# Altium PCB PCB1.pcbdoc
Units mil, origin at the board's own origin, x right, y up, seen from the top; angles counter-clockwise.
Board outline 1023.62 x 2480.31 mil, 4 copper layers (Top Layer, Inner2, Inner3, Bottom Layer), stack 62.447 mil thick; 59 components, 53 nets, 271 pads, 114 vias.
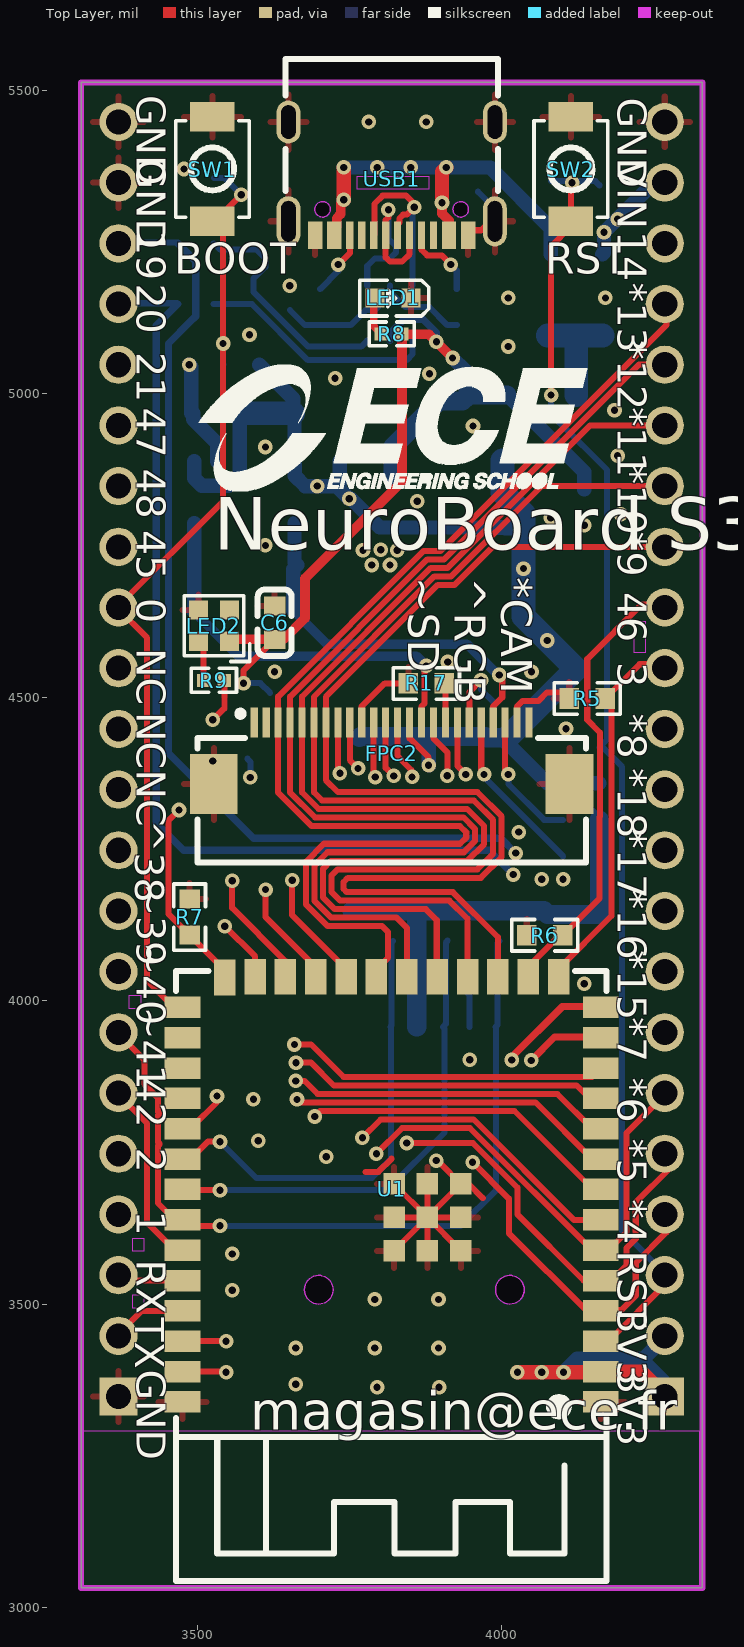
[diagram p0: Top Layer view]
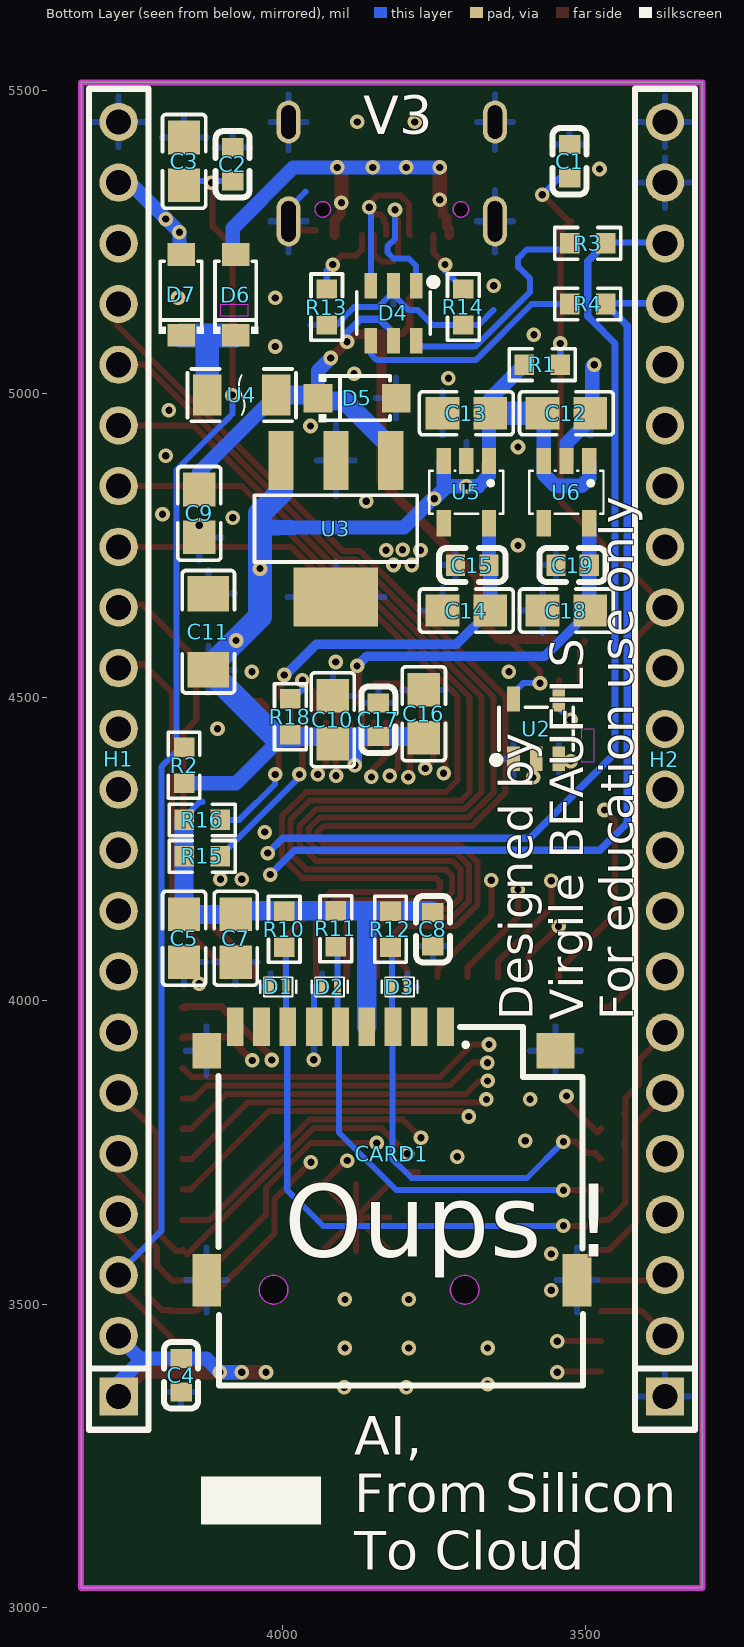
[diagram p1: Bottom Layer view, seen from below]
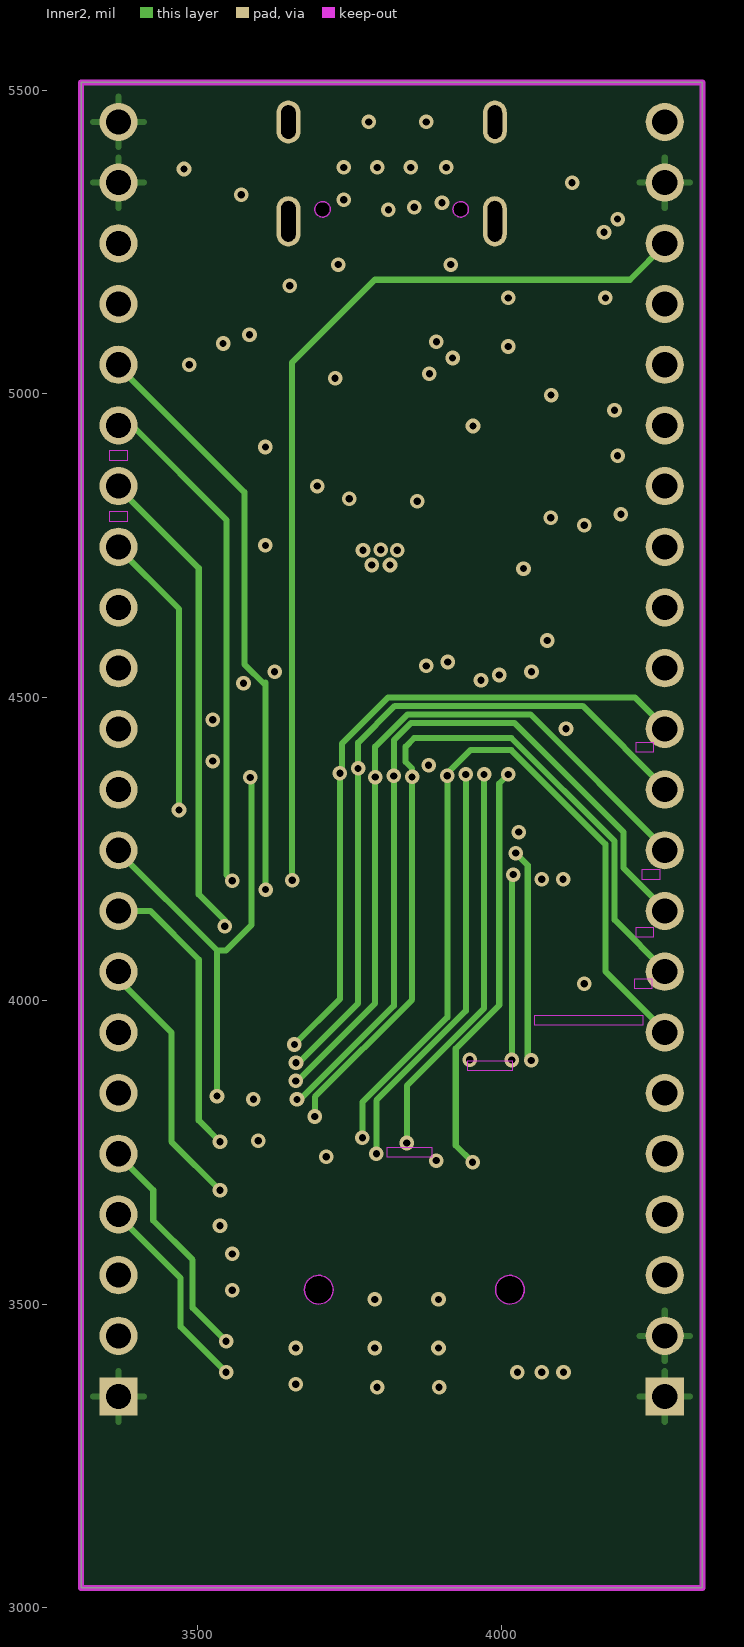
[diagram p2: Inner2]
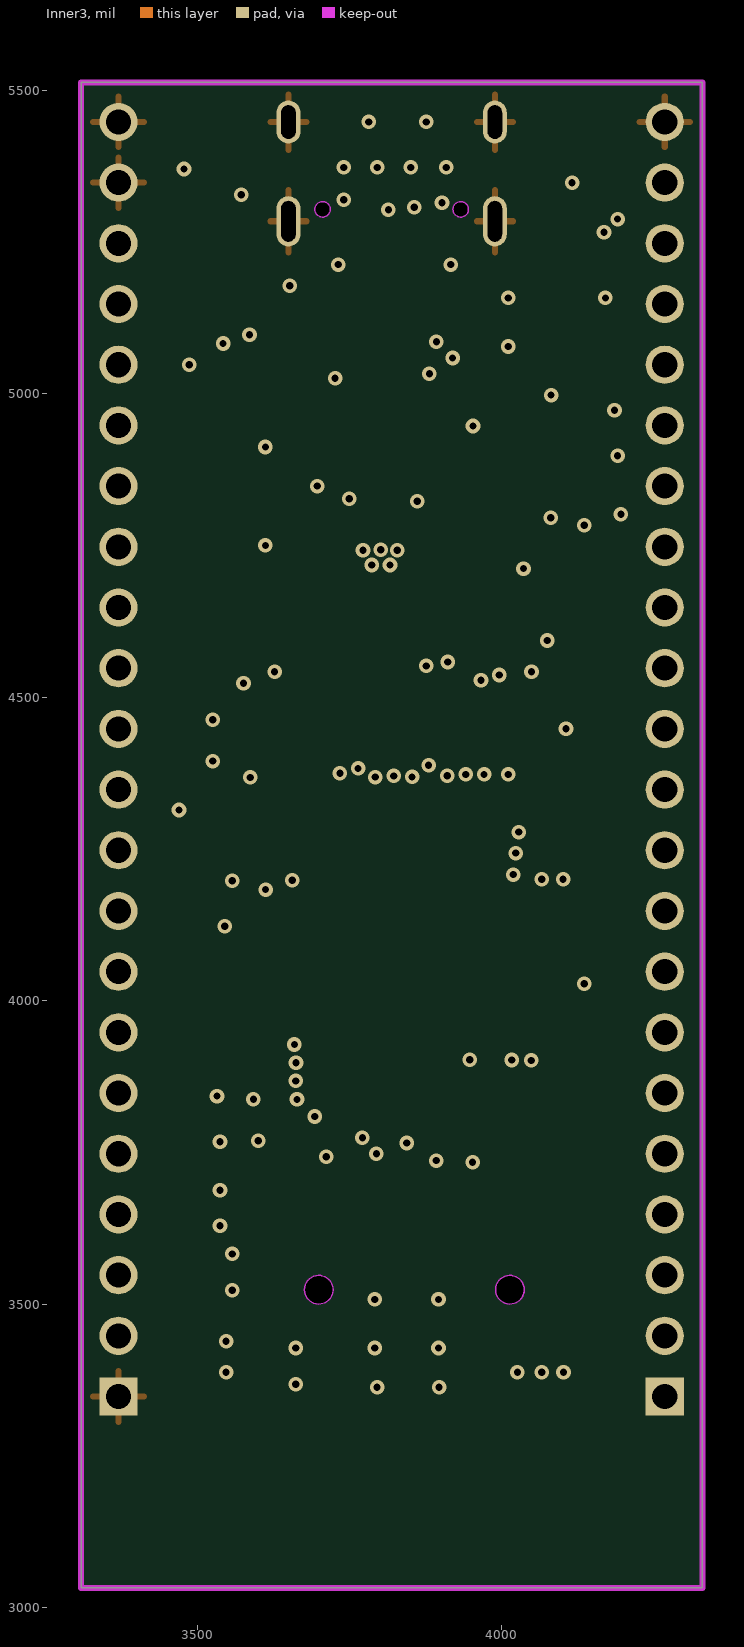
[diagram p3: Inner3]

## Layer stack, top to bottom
Top Layer: signal copper 1.378
Dielectric1: surface 8.283, 7628 RC49% 8.6mil, Dk 0
Inner2: signal copper 0.598
Dielectric2: surface 41.929, 1.1mm H/HOZ Copper, Dk 0
Inner3: signal copper 0.598
Dielectric3: surface 8.283, 7628 RC49% 8.6mil, Dk 0
Bottom Layer: signal copper 1.378

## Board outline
3307.99,5513.17 3307.99,3032.85 4331.61,3032.85 4331.61,5513.17

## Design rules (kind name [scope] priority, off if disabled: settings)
BoardOutlineClearance copperThickness1oz [All] p0: genericclearance=10 ignorepadtopadclearanceinfootprint=FALSE except(0: Arc-SplitContinuation Track-SplitContinuation SMDPad-SplitContinuation THPad-SplitContinuation Via-SplitContinuation Fill-SplitContinuation Poly-SplitContinuation Region-SplitContinuation Text-SplitContinuation)
BoardOutlineClearance copperThickness2oz [All] p0: genericclearance=10 ignorepadtopadclearanceinfootprint=FALSE except(0: Arc-SplitContinuation Track-SplitContinuation SMDPad-SplitContinuation THPad-SplitContinuation Via-SplitContinuation Fill-SplitContinuation Poly-SplitContinuation Region-SplitContinuation Text-SplitContinuation)
BoardOutlineClearance Plane_innerPlane [All] p0: genericclearance=10 ignorepadtopadclearanceinfootprint=FALSE except(0: Arc-SplitContinuation Track-SplitContinuation SMDPad-SplitContinuation THPad-SplitContinuation Via-SplitContinuation Fill-SplitContinuation Poly-SplitContinuation Region-SplitContinuation Text-SplitContinuation)
BoardOutlineClearance Copper_copperRegion [All] p0: genericclearance=10 ignorepadtopadclearanceinfootprint=FALSE except(0: Arc-SplitContinuation Track-SplitContinuation SMDPad-SplitContinuation THPad-SplitContinuation Via-SplitContinuation Fill-SplitContinuation Poly-SplitContinuation Region-SplitContinuation Text-SplitContinuation)
BoardOutlineClearance otherClearance [All] p0: genericclearance=10 ignorepadtopadclearanceinfootprint=FALSE except(0: Arc-SplitContinuation Track-SplitContinuation SMDPad-SplitContinuation THPad-SplitContinuation Via-SplitContinuation Fill-SplitContinuation Poly-SplitContinuation Region-SplitContinuation Text-SplitContinuation)
Clearance copperThickness1oz [All] p1: gap=7 ignorepadtopadclearanceinfootprint=FALSE
Clearance copperThickness2oz [All] p1: gap=7 ignorepadtopadclearanceinfootprint=FALSE
Clearance Plane_innerPlane [All] p1: gap=7 ignorepadtopadclearanceinfootprint=FALSE
Clearance Copper_copperRegion [All] p1: gap=7 ignorepadtopadclearanceinfootprint=FALSE
Clearance otherClearance [All] p1: gap=7 ignorepadtopadclearanceinfootprint=FALSE
DiffPairsRouting differentialPair [All] p1: maxuncoupledlength=10 minlimit=6 maxlimit=Infinity mostfreqgap=6 toplayer_minwidth=5 toplayer_prefwidth=10 toplayer_maxwidth=100 bottomlayer_minwidth=5 bottomlayer_prefwidth=10 bottomlayer_maxwidth=100 midlayer2_minwidth=5 midlayer2_prefwidth=10 midlayer2_maxwidth=100 midlayer3_minwidth=5 midlayer3_prefwidth=10 midlayer3_maxwidth=100
PasteMaskExpansion pasteMaskExpansion [All] p1: expansion=0
PlaneConnect innerPlane [All] p1: planeconnectstyle=Relief reliefexpansion=20 reliefentries=4 reliefconductorwidth=10 reliefairgap=10
PolygonConnect copperRegion [All] p1: connectstyle=Relief reliefentries=4 reliefconductorwidth=10 polygonreliefangle="90 Angle" airgapwidth=10
RoutingVias viaSize [All] p1: viastyle="Through Hole" holewidth=12.0078 minholewidth=11.811 maxholewidth=248.0314 width=12.0078 minwidth=11.811 maxwidth=248.0314
SolderMaskExpansion solderMaskExpansion [IsVia] p1: useseparateexpansions=TRUE expansion=-1000 expansionbottom=-1000
SolderMaskExpansion solderMaskExpansion [All] p2: useseparateexpansions=TRUE expansion=2 expansionbottom=2
Width copperThickness1oz [All] p1: maxlimit=100 minlimit=5 preferedwidth=10
Width copperThickness2oz [All] p1: maxlimit=100 minlimit=8 preferedwidth=10

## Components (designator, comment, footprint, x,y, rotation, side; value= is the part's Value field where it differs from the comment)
C1 "100nF" C0603 3526.89,5382.99 r90 bottom
C2 "100nF" C0603 4081.89,5377.99 r90 bottom
C3 "1uF" C0805 4161.89,5382.99 r270 bottom
C4 "100nF" C0603 4166.89,3382.99 r90 bottom
C5 "22uF" C0805 4161.89,4102.99 r90 bottom
C6 "100nF" C0603 3626.89,4622.99 r270 top
C7 "10uF" C0805 4076.89,4102.99 r270 bottom
C8 "100nF" C0603 3751.89,4117.99 r270 bottom
C9 "10uF" C0805 4136.89,4802.99 r270 bottom
C10 "10uF" C0805 3916.89,4462.99 r90 bottom
C11 "47uF" C1206 4121.89,4607.99 r270 bottom
C12 "1uF" C0805 3531.89,4967.99 r0 bottom
C13 "1uF" C0805 3696.89,4967.99 r180 bottom
C14 "10uF" C0805 3696.89,4642.99 r0 bottom
C15 "100nF" C0603 3686.89,4717.99 r0 bottom
C16 "10uF" C0805 3766.89,4472.99 r90 bottom
C17 "100nF" C0603 3841.89,4462.99 r90 bottom
C18 "10uF" C0805 3531.89,4642.99 r0 bottom
C19 "100nF" C0603 3521.89,4717.99 r0 bottom
CARD1 "TF PUSH" TF-SMD_TF-PUSH 3819.65,3748.39 r180 bottom locked
D1 "LESD8D3.3CAT5G" SOD-882_L1.0-W0.6-BI 4006.89,4022.99 r180 bottom
D2 "LESD8D3.3CAT5G" SOD-882_L1.0-W0.6-BI 3921.89,4022.99 r180 bottom
D3 "LESD8D3.3CAT5G" SOD-882_L1.0-W0.6-BI 3806.89,4022.99 r0 bottom
D4 "USBLC6-2SC6" SOT-23-6_L2.9-W1.6-P0.95-LS2.8-BL 3816.89,5132.99 r0 bottom
D5 "SMF5.0A" SOD-123FL_L2.7-W1.8-LS3.8-RD 3876.89,4992.99 r180 bottom
D6 "DSS34" SOD-123_L2.8-W1.8-LS3.7-RD-2 4076.89,5162.99 r90 bottom
D7 "DSS34" SOD-123_L2.8-W1.8-LS3.7-RD-2 4166.89,5162.99 r90 bottom
FPC2 "FPC-05F-24PH20" FPC-SMD_24P-P0.50_FPC-05F-24PH20 3819.65,4407.99 r0 top locked
H1 "B-2100S22P-A110" HDR-TH_22P-P2.54-V-M 4269.65,4397.99 r90 bottom locked
H2 "B-2100S22P-A110" HDR-TH_22P-P2.54-V-M 3369.65,4397.99 r90 bottom locked
LED1 "KT-0603B" LED0603-RD 3821.89,5157.99 r180 top
LED2 "SK6805-EC20" LED-SMD_4P-L2.0-W2.0-BR 3526.89,4617.99 r0 top
R1 "10kΩ" R0603 3571.89,5047.99 r0 bottom
R2 "10kΩ" R0603 4161.89,4387.99 r270 bottom
R3 "" R0603 3496.89,5247.99 r180 bottom
R4 "" R0603 3496.89,5147.99 r180 bottom
R5 "10kΩ" R0603 4141.89,4497.99 r180 top
R6 "10kΩ" R0603 4071.89,4107.99 r180 top
R7 "10kΩ" R0603 3486.89,4137.99 r270 top
R8 "1kΩ" R0402 3819.65,5098.78 r0 top
R9 "220Ω" R0402 3526.89,4527.99 r0 top
R10 "10kΩ" R0603 3996.89,4117.99 r270 bottom
R11 "10kΩ" R0603 3911.89,4118.67 r270 bottom
R12 "10kΩ" R0603 3821.89,4117.99 r270 bottom
R13 "5.1kΩ" R0603 3926.89,5142.99 r90 bottom
R14 "5.1kΩ" R0603 3701.89,5142.99 r90 bottom
R15 "2.7kΩ" R0603 4131.89,4237.99 r0 bottom
R16 "2.7kΩ" R0603 4131.89,4297.99 r0 bottom
R17 "10kΩ" R0603 3876.89,4522.99 r180 top
R18 "10kΩ" R0603 3986.89,4467.99 r270 bottom
SW1 "TS-1088-AR02016" SW-SMD_L3.9-W3.0-P4.45 3524.37,5370.43 r270 top
SW2 "TS-1088-AR02016" SW-SMD_L3.9-W3.0-P4.45 4114.92,5370.43 r270 top locked
U1 "2.4GHz" WIRELM-SMD_ESP32-S3-WROOM-1 3819.65,3689.33 r180 top locked
U2 "SN74AHCT1G125DBVR(UMW)" SOT-23-5_L3.0-W1.5-P0.95-LS2.8-BL 3581.89,4447.99 r180 bottom
U3 "AP7361C-33E-13" SOT-223_L6.5-W3.5-P2.30-LS7.0-BR 3911.89,4777.99 r90 bottom
U4 "MF-NSMF150-2" F1206 4066.89,4997.99 r0 bottom
U5 "ME6211C28M5G-N" SOT-23-5_L3.0-W1.7-P0.95-LS2.8-BR 3696.89,4837.99 r90 bottom
U6 "ME6211C15M5G-N" SOT-23-5_L3.0-W1.7-P0.95-LS2.8-BR 3531.89,4837.99 r90 bottom
USB1 "TYPE-C16PIN" USB-C-SMD_TYPE-C16PIN 3819.65,5354.69 r180 top locked

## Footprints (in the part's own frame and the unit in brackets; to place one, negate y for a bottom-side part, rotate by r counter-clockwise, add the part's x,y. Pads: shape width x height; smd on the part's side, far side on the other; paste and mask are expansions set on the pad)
C0603 [mm]
  rect 0.8x0.9 smd: 1(-0.7,0) 2(0.7,0)
  silkscreen extent -1.39,-0.71 1.39,0.71
C0805 [mm]
  rect 1.41x1.35 smd paste-100 mask+0.051: 1(-1,0) 2(1,0)
  silkscreen extent -1.96,-0.9 1.96,0.9
C1206 [mm]
  rect 1.485x1.728 smd paste-100 mask+0.051: 1(-1.593,0) 2(1.593,0)
  silkscreen extent -2.56,-1.09 2.56,1.09
F1206 [mm]
  rect 1.19x1.728 smd: 1(-1.445,0) 2(1.445,0)
  silkscreen extent -2.27,-1.09 2.27,1.09
FPC-SMD_24P-P0.50_FPC-05F-24PH20 [mm]
  rect 0.3x1.25 smd paste+0 mask+0.05: 1(-5.75,1.288) 2(-5.25,1.288) 3(-4.75,1.288) 4(-4.25,1.288) 5(-3.75,1.288) 6(-3.25,1.288) 7(-2.75,1.288) 8(-2.25,1.288) 9(-1.75,1.288) 10(-1.25,1.288) 11(-0.75,1.288) 12(-0.25,1.288) 13(0.25,1.288) 14(0.75,1.288) 15(1.25,1.288) 16(1.75,1.288) 17(2.25,1.288) 18(2.75,1.288) 19(3.25,1.288) 20(3.75,1.288) 21(4.25,1.288) 22(4.75,1.288) 23(5.25,1.288) 24(5.75,1.288)
  rect 2x2.5 smd paste+0 mask+0.05: 25(7.44,-1.288) 26(-7.44,-1.288)
  silkscreen extent -8.13,-4.57 8.13,1.78
HDR-TH_22P-P2.54-V-M [mm]
  rect 1.6x1.6 hole 1.05: 1(-26.67,0)
  round 1.6 hole 1.05: 2(-24.13,0) 3(-21.59,0) 4(-19.05,0) 5(-16.51,0) 6(-13.97,0) 7(-11.43,0) 8(-8.89,0) 9(-6.35,0) 10(-3.81,0) 11(-1.27,0) 12(1.27,0) 13(3.81,0) 14(6.35,0) 15(8.89,0) 16(11.43,0) 17(13.97,0) 18(16.51,0) 19(19.05,0) 20(21.59,0) 21(24.13,0) 22(26.67,0)
  silkscreen extent -28.06,-1.25 28.06,1.25
LED0603-RD [mm]
  rect 0.8x0.8 smd: 1(-0.749,0) 2(0.749,0)
  silkscreen extent -1.49,-0.75 1.39,0.76
LED-SMD_4P-L2.0-W2.0-BR [mm]
  rect 0.8x0.8 smd: 1(0.65,-0.65) 2(0.65,0.65) 3(-0.65,0.65) 4(-0.65,-0.65)
  silkscreen extent -1.25,-1.5 1.5,1.25
R0402 [mm]
  rect 0.566x0.54 smd paste-100 mask+0.051: 1(-0.433,0) 2(0.433,0)
  silkscreen extent -0.94,-0.5 0.94,0.5
R0603 [mil]
  rect 31.75x34.02 smd paste-3937.01 mask+2: 1(-29.66,0) 2(29.66,0)
  silkscreen extent -55,-26 55,26
SOD-123_L2.8-W1.8-LS3.7-RD-2 [mm]
  rect 0.95x1.15 smd: 1(-1.692,0) 2(1.692,0)
  silkscreen extent -1.63,-0.94 1.41,0.94
SOD-123FL_L2.7-W1.8-LS3.8-RD [mm]
  rect 1.2x1.2 smd: 1(-1.635,0) 2(1.635,0)
  silkscreen extent -1.6,-1 1.38,1
SOD-882_L1.0-W0.6-BI [mm]
  rect 0.3x0.6 smd paste+0 mask+0.05: 1(-0.325,0) 2(0.325,0)
  silkscreen extent -0.75,-0.4 0.75,0.4
SOT-23-5_L3.0-W1.5-P0.95-LS2.8-BL [mm]
  rect 0.532x1.045 smd: 1(-0.95,-1.25) 2(0,-1.25) 3(0.95,-1.25) 4(0.95,1.25) 5(-0.95,1.25)
  silkscreen extent -1.82,-1.45 1.55,0.9
SOT-23-5_L3.0-W1.7-P0.95-LS2.8-BR [mm]
  rect 1.1x0.6 smd: 1(1.3,-0.95) 2(1.3,0) 3(1.3,0.95) 4(-1.3,0.95) 5(-1.3,-0.95)
  silkscreen extent -0.9,-1.55 0.9,1.55
SOT-23-6_L2.9-W1.6-P0.95-LS2.8-BL [mil]
  rect 20.95x42.2 smd: 1(-37.4,-45.24) 2(0,-45.24) 3(37.4,-45.24) 4(37.4,45.24) 5(0,45.24) 6(-37.4,45.24)
  silkscreen extent -72,-57 61,35
SOT-223_L6.5-W3.5-P2.30-LS7.0-BR [mm]
  rect 2.465x1.05 smd: 1(2.857,-2.3) 2(2.857,0) 3(2.857,2.3)
  rect 2.465x3.54 smd: 4(-2.857,0)
  silkscreen extent -1.4,-3.4 1.4,3.4
SW-SMD_L3.9-W3.0-P4.45 [mm]
  rect 1.23x1.86 smd: 1(-2.185,0) 2(2.185,0)
  silkscreen extent -2.03,-1.54 2.03,1.54
TF-SMD_TF-PUSH [mm]
  rect 0.7x1.6 smd: 1(2.25,5.3) 2(1.15,5.3) 3(0.05,5.3) 4(-1.05,5.3) 5(-2.15,5.3) 6(-3.25,5.3) 7(-4.35,5.3) 8(-5.45,5.3) CD(-6.55,5.3)
  rect 1.2x1.5 smd: 10(-7.75,4.3)
  rect 1.2x2.2 smd: 11(-7.75,-5.3) 12(7.75,-5.3)
  rect 1.6x1.5 smd: 13(6.85,4.3)
  Board Outline Layer circle w0.003: c-4.95,-5.7 r0.6
  Board Outline Layer circle w0.003: c3.05,-5.7 r0.6
  Board Outline Layer region: -5.55,-5.7 -5.491,-5.96 -5.324,-6.169 -5.083,-6.285 -4.816,-6.285 -4.576,-6.169 -4.409,-5.96 -4.35,-5.7 -4.35,-5.7 -4.409,-5.44 -4.576,-5.231 -4.816,-5.115 -5.083,-5.115 -5.324,-5.231 -5.491,-5.44 -5.55,-5.7
  Board Outline Layer region: -5.55,-5.7 -5.541,-5.804 -5.514,-5.905 -5.47,-6 -5.41,-6.086 -5.336,-6.16 -5.25,-6.22 -5.155,-6.264 -5.054,-6.291 -4.95,-6.3 -4.846,-6.291 -4.745,-6.264 -4.65,-6.22 -4.564,-6.16 -4.49,-6.086 -4.43,-6 -4.386,-5.905 -4.359,-5.804 -4.35,-5.7 -4.359,-5.596 -4.386,-5.495 -4.43,-5.4 -4.49,-5.314 -4.564,-5.24 -4.65,-5.18 -4.745,-5.136 -4.846,-5.109 -4.95,-5.1 -5.054,-5.109 -5.155,-5.136 -5.25,-5.18 -5.336,-5.24 -5.41,-5.314 -5.47,-5.4 -5.514,-5.495 -5.541,-5.596
  Board Outline Layer region: 2.45,-5.7 2.509,-5.96 2.676,-6.169 2.917,-6.285 3.184,-6.285 3.424,-6.169 3.591,-5.96 3.65,-5.7 3.65,-5.7 3.591,-5.44 3.424,-5.231 3.184,-5.115 2.917,-5.115 2.676,-5.231 2.509,-5.44 2.45,-5.7
  Board Outline Layer region: 2.45,-5.7 2.459,-5.804 2.486,-5.905 2.53,-6 2.59,-6.086 2.664,-6.16 2.75,-6.22 2.845,-6.264 2.946,-6.291 3.05,-6.3 3.154,-6.291 3.255,-6.264 3.35,-6.22 3.436,-6.16 3.51,-6.086 3.57,-6 3.614,-5.905 3.641,-5.804 3.65,-5.7 3.641,-5.596 3.614,-5.495 3.57,-5.4 3.51,-5.314 3.436,-5.24 3.35,-5.18 3.255,-5.136 3.154,-5.109 3.05,-5.1 2.946,-5.109 2.845,-5.136 2.75,-5.18 2.664,-5.24 2.59,-5.314 2.53,-5.4 2.486,-5.495 2.459,-5.596
  Multi-Layer board cut-out: -5.55,-5.7 -5.491,-5.96 -5.324,-6.169 -5.083,-6.285 -4.816,-6.285 -4.576,-6.169 -4.409,-5.96 -4.35,-5.7 -4.35,-5.7 -4.409,-5.44 -4.576,-5.231 -4.816,-5.115 -5.083,-5.115 -5.324,-5.231 -5.491,-5.44 -5.55,-5.7
  Multi-Layer board cut-out: 2.45,-5.7 2.509,-5.96 2.676,-6.169 2.917,-6.285 3.184,-6.285 3.424,-6.169 3.591,-5.96 3.65,-5.7 3.65,-5.7 3.591,-5.44 3.424,-5.231 3.184,-5.115 2.917,-5.115 2.676,-5.231 2.509,-5.44 2.45,-5.7
  silkscreen extent -7.26,-9.7 8,5.3
USB-C-SMD_TYPE-C16PIN [mm]
  oval 1x2.1 hole 0.6 slot 1.7 at 90 deg: 1(-4.32,1.787) 2(4.32,1.787)
  oval 1x1.8 hole 0.6 slot 1.4 at 90 deg: 3(-4.32,-2.362) 4(4.32,-2.362)
  rect 0.6x1.15 smd paste-100 mask+0.051: A1B12(-3.2,2.362) A4B9(-2.4,2.362) B1A12(3.2,2.362) B4A9(2.4,2.362)
  rect 0.3x1.15 smd paste-100 mask+0.051: A5(-1.25,2.362) A6(-0.25,2.362) A7(0.25,2.362) A8(1.25,2.362) B5(1.75,2.362) B6(0.75,2.362) B7(-0.75,2.362) B8(-1.75,2.362)
  Board Outline Layer circle w0.003: c2.89,1.288 r0.325
  Board Outline Layer circle w0.003: c-2.89,1.288 r0.325
  Board Outline Layer region: 2.565,1.288 2.597,1.429 2.687,1.542 2.818,1.605 2.962,1.605 3.093,1.542 3.183,1.429 3.215,1.288 3.215,1.288 3.183,1.147 3.093,1.034 2.962,0.971 2.818,0.971 2.687,1.034 2.597,1.147 2.565,1.288
  Board Outline Layer region: 2.565,1.288 2.574,1.366 2.602,1.439 2.647,1.504 2.705,1.555 2.775,1.592 2.851,1.611 2.929,1.611 3.005,1.592 3.075,1.555 3.133,1.504 3.178,1.439 3.206,1.366 3.215,1.288 3.206,1.21 3.178,1.137 3.133,1.073 3.075,1.021 3.005,0.984 2.929,0.965 2.851,0.965 2.775,0.984 2.705,1.021 2.647,1.073 2.602,1.137 2.574,1.21
  Board Outline Layer region: -3.215,1.288 -3.183,1.429 -3.093,1.542 -2.962,1.605 -2.818,1.605 -2.687,1.542 -2.597,1.429 -2.565,1.288 -2.565,1.288 -2.597,1.147 -2.687,1.034 -2.818,0.971 -2.962,0.971 -3.093,1.034 -3.183,1.147 -3.215,1.288
  Board Outline Layer region: -3.215,1.288 -3.206,1.366 -3.178,1.439 -3.133,1.504 -3.075,1.555 -3.005,1.592 -2.929,1.611 -2.851,1.611 -2.775,1.592 -2.705,1.555 -2.647,1.504 -2.602,1.439 -2.574,1.366 -2.565,1.288 -2.574,1.21 -2.602,1.137 -2.647,1.073 -2.705,1.021 -2.775,0.984 -2.851,0.965 -2.929,0.965 -3.005,0.984 -3.075,1.021 -3.133,1.073 -3.178,1.137 -3.206,1.21
  Multi-Layer board cut-out: 2.565,1.288 2.597,1.429 2.687,1.542 2.818,1.605 2.962,1.605 3.093,1.542 3.183,1.429 3.215,1.288 3.215,1.288 3.183,1.147 3.093,1.034 2.962,0.971 2.818,0.971 2.687,1.034 2.597,1.147 2.565,1.288
  Multi-Layer board cut-out: -3.215,1.288 -3.183,1.429 -3.093,1.542 -2.962,1.605 -2.818,1.605 -2.687,1.542 -2.597,1.429 -2.565,1.288 -2.565,1.288 -2.597,1.147 -2.687,1.034 -2.818,0.971 -2.962,0.971 -3.093,1.034 -3.183,1.147 -3.215,1.288
  silkscreen extent -4.45,-5 4.45,0.52
WIRELM-SMD_ESP32-S3-WROOM-1 [mm]
  rect 1.5x0.9 smd paste+0 mask+0.05: 1(-8.75,8.895) 2(-8.75,7.625) 3(-8.75,6.355) 4(-8.75,5.085) 5(-8.75,3.815) 6(-8.75,2.545) 7(-8.75,1.275) 8(-8.75,0.005) 9(-8.75,-1.265) 10(-8.75,-2.535) 11(-8.75,-3.805) 12(-8.75,-5.075) 13(-8.75,-6.345) 14(-8.75,-7.615) 27(8.75,-7.615) 28(8.75,-6.345) 29(8.75,-5.075) 30(8.75,-3.805) 31(8.75,-2.535) 32(8.75,-1.265) 33(8.75,0.005) 34(8.75,1.275) 35(8.75,2.545) 36(8.75,3.815) 37(8.75,5.085) 38(8.75,6.355) 39(8.75,7.625) 40(8.75,8.895)
  rect 0.9x1.5 smd paste+0 mask+0.05: 15(-6.985,-8.895) 16(-5.715,-8.895) 17(-4.445,-8.895) 18(-3.175,-8.895) 19(-1.905,-8.895) 20(-0.635,-8.895) 21(0.635,-8.895) 22(1.905,-8.895) 23(3.175,-8.895) 24(4.445,-8.895) 25(5.715,-8.895) 26(6.985,-8.865)
  rect 0.9x0.9 smd: 41(-2.9,2.575) 41(-2.9,-0.225) 41(-2.9,1.175) 41(-1.5,2.575) 41(-1.5,1.175) 41(-1.5,-0.225) 41(-0.1,2.575) 41(-0.1,1.175) 41(-0.1,-0.225)
  silkscreen extent -9,-9.14 9.02,16.39

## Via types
v1: diameter 24.02, hole 12, Top Layer to Bottom Layer, 114 vias

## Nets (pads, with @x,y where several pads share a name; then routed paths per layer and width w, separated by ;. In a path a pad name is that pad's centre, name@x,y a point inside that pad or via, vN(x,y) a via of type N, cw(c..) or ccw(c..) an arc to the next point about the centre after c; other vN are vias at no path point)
$1N1026: R14.2 USB1.B5 | length 109.3
  Top Layer w10: v1(3731.89,5212.99) 3750.75,5231.85 USB1.B5
  Bottom Layer w10: R14.2 3731.89,5202.65 v1(3731.89,5212.99)
$1N1027: R13.2 USB1.A5 | length 127.3
  Top Layer w10: USB1.A5 3868.86,5237.29 3878.09,5228.05 3902.48,5228.05 3916.89,5213.64 v1(3916.89,5212.99)
  Bottom Layer w10: v1(3916.89,5212.99) 3926.89,5202.99 R13.2
$1N8618: LED2.4 R9.1 | length 67.9
  Top Layer w10: LED2.4 3509.85,4583.84 R9.1
$1N9964: FPC2.19 R18.1 | length 120.9
  Top Layer w10: FPC2.19 3947.6,4508.7 v1(3966.89,4527.99)
  Bottom Layer w10: v1(3966.89,4527.99) 3966.89,4512.65 R18.1@3986.89,4492.65
$1N10048: FPC2.17 R17.1 | length 65
  Top Layer w10: R17.1 3908.23,4521.31 FPC2.17
$1N22783: LED1.2 R8.1 | length 64.2
  Top Layer w11.81: LED1.2@3790.16,5157.83 3790.16,5111.23 R8.1
$1N35174: D6.1 D7.1 U4.2 | length 189.4
  Bottom Layer w39.37: D6.1 4126.36,5096.36 ; U4.2 4123.78,5093.78 4126.36,5096.36 ; D7.1 4126.36,5096.36
+1.5V: C18.1 C19.1 FPC2.15 U6.5 | length 663.1
  Top Layer w10: FPC2.15 3868.86,4485.05 3874.09,4490.28 3874.09,4548.86 v1(3876.89,4551.66)
  Bottom Layer w15.75: C18.1 3567.52,4567.99 3860.56,4567.99 v1(3876.89,4551.66)
  Bottom Layer w23.62: C18.1 3494.49,4644.96 U6.5
+2.8V: C14.1 C15.1 FPC2.21 U5.5 | length 618.3
  Top Layer w10: FPC2.21 3986.97,4485.05 4001.89,4499.97 4001.89,4531.71 v1(3996.89,4536.71)
  Bottom Layer w15.75: C14.1 3712.76,4587.76 3943.71,4587.76 3994.76,4536.71 v1(3996.89,4536.71)
  Bottom Layer w23.62: C14.1 3657.52,4711.18 3664.33,4717.99 3659.49,4722.83 U5.5
+3.3V: C4.2 C5.2 C7.1 C8.1 C10.1 C11.2 C12.2 C13.2 C16.1 C17.1 CARD1.4 FPC2.14 H1.1 H1.2 R1.2 R2.2 R10.1 R11.1 R12.1 R15.2 R16.2 R18.2 U1.2 U3.3 U5.1 U5.3 U6.1 U6.3 | length 3441.4
  Top Layer w10: FPC2.14 3849.17,4432.33 3880.55,4400.95 v1(3880.55,4387.99)
  Top Layer w23.62: v1(4026.89,3387.99) v1(4066.89,3387.99) v1(4102.86,3387.99) 4162.99,3387.99 U1.2 4231.26,3389.14 H1.1@4272.4,3347.99
  Bottom Layer w10: 4131.89,4327.99 4136.41,4327.99 R16.2@4161.89,4302.51
  Bottom Layer w23.62: U6.1 3494.49,4861.12 3506.89,4848.72 3550.35,4848.72 3569.29,4867.66 U6.3 C12.2@3569.29,4963.98 ; R1.2 3657.52,4992.02 C13.2 3659.49,4966.02 U5.1 ; U5.1@3659.78,4883.88 3659.78,4865.15 3676.94,4847.99 v1(3696.89,4847.99) 3726.89,4847.99 3734.29,4855.39 ; U5.3 3734.29,4855.39 ; 3878.6,4435.43 3880.55,4433.49 v1(3880.55,4387.99) ; R18.2@4001.55,4433.33 4076.55,4358.33 R2.2 ; 4036.89,4779.73 3800,4779.73 3752.72,4827 v1(3749.92,4827) 3734.29,4842.64 3734.29,4855.39 ; v1(4066.89,3387.99) v1(4102.86,3387.99) 4125.42,3410.55 C4.2 4234.96,3410.55 ; H1.1@4272.4,3347.99 4267.4,3352.99 4267.4,3373.11 4234.96,3405.55 4234.96,3410.55 ; H1.2@4272.4,3447.99 4234.96,3410.55
  Bottom Layer w31.5: C8.1@3754.63,4148.29 3860.52,4148.29 ; C16.1 3768.7,4435.43 C17.1 3878.6,4435.43 3974.45,4435.43 3976.55,4433.33 R18.2@4001.55,4433.33 ; CARD1.4 3860.99,4147.82 3860.52,4148.29 ; R16.2 4161.89,4297.65 C5.2 C7.1 4070.96,4148.29 R11.1 3860.52,4148.29
  Bottom Layer w39.37: C12.2 C13.2 ; U3.3 4002.44,4837.44 4036.89,4802.99 4036.89,4779.73 v1(4036.89,4712.16) 4036.89,4632.99 v1(4076.26,4593.62) 4121.89,4547.99 C11.2 4009.93,4433.33
  other v1: 4106.89,4447.99 4050.1,4542.3
+VIN: D7.2 H1.21 | length 171.6
  Bottom Layer w23.62: D7.2 4169.53,5232.26 v1(4169.53,5266.07) 4251.45,5347.99 H1.21
  other v1: 4191.89,5287.99
+VSYS: C6.2 C9.1 D4.5 D5.1 LED2.1 R8.2 U2.5 U3.1 U4.1 | length 1598.4
  Top Layer w10: v1(3575.52,4523.31) 3575.52,4544.06 C6.2
  Top Layer w15.75: LED2.1 3555.52,4595.43 C6.2 3641.89,4595.43 3676.89,4630.43 3676.89,4695.86 3836.69,4855.66 R8.2 ; R8.2@3837.47,5097.99 3881.16,5097.99 v1(3893.45,5085.7) v1(3920.09,5059.06)
  Bottom Layer w10: v1(3575.52,4523.31) 3603.18,4523.31 U2.5@3619.29,4507.2
  Bottom Layer w11.81: D4.5 3816.89,5100.04 3839.84,5122.99 3871.16,5122.99 3893.45,5100.7 v1(3893.45,5085.7)
  Bottom Layer w23.62: v1(3920.09,5059.06) 3941.26,5037.89 D5.1 ; U4.1 4136.89,4871.1 C9.1
  Bottom Layer w31.5: U3.1 U3.1@3821.89,4889.94 ; U3.1@3821.89,4861.55 U3.1@3821.89,4889.94 ; U4.1 3946.26,4997.99 D5.1 3936.26,4987.99 3896.89,4987.99 3821.89,4912.99 U3.1@3821.89,4889.94
+VUSB: D6.2 USB1.A4B9 USB1.B4A9 | length 662.4
  Top Layer w15.75: USB1.B4A9 3725.16,5271.68 3728.86,5275.38 3728.86,5289.27 3735.66,5296.08 3735.66,5314.74 v1(3740.66,5319.74) ; v1(3902.64,5315.06) 3902.64,5297.07 3914.14,5285.57 USB1.A4B9
  Top Layer w23.62: v1(3740.66,5319.74) v1(3740.66,5372.99) ; v1(3902.64,5315.06) 3902.64,5365.98 v1(3909.65,5372.99)
  Bottom Layer w23.62: v1(3740.66,5372.99) v1(3795.85,5372.99) v1(3851.26,5372.99) v1(3909.65,5372.99) 3981.89,5372.99 4081.89,5272.99 D6.2@4081.89,5229.92
DN: D4.1 USB1.A7 USB1.B7 | length 323.7
  Top Layer w10: v1(3814.35,5303.45) 3814.35,5290.62 3809.81,5286.07 USB1.A7 3809.81,5225.08 3816.89,5217.99 3836.89,5217.99 3849.18,5230.28 USB1.B7
  Bottom Layer w10: D4.1 3779.49,5210.59 3791.89,5222.99 3816.89,5222.99 3826.89,5232.99 3826.89,5242.99 3814.35,5255.53 v1(3814.35,5303.45)
DNF: D4.6 R3.1 | length 387.7
  Bottom Layer w10: R3.1 3536.55,5237.99 3596.89,5237.99 3611.46,5223.42 3611.46,5209.28 3591.89,5189.71 3591.89,5167.99 3682.13,5077.75 3769.49,5077.75 D4.6
DP: D4.3 USB1.A6 USB1.B6 | length 324.9
  Top Layer w10: USB1.B6 3791.36,5262.92 3791.36,5312.97 3804.83,5326.44 3843.44,5326.44 3856.89,5312.99 v1(3856.89,5307.31) 3844.88,5295.3 3838.72,5295.3 3832.29,5288.86 3832.29,5282.7 3829.49,5279.9 USB1.A6
  Bottom Layer w10: D4.3 3854.29,5304.71 v1(3856.89,5307.31)
DPF: D4.4 R4.1 | length 392.2
  Bottom Layer w10: R4.1 3589.26,5147.99 3681.59,5055.67 3844.29,5055.67 3854.29,5065.67 D4.4
GND: C1.2 C2.2 C3.1 C4.1 C5.1 C6.1 C7.2 C8.2 C9.2 C10.2 C11.1 C12.1 C13.1 C14.2 C15.2 C16.2 C17.2 C18.2 C19.2 CARD1.6 CARD1.10 CARD1.11 CARD1.12 CARD1.13 D1.1 D2.1 D3.1 D4.2 D5.2 FPC2.10 FPC2.23 FPC2.25 FPC2.26 H1.22 H2.1 H2.21 H2.22 LED1.1 LED2.3 R5.2 R6.2 R7.1 R13.1 R14.1 R17.2 SW1.1 SW2.1 U1.1 U1.40 U1.41 U2.1 U2.3 U3.2 U3.4 U5.2 U6.2 USB1.1 USB1.2 USB1.3 USB1.4 USB1.A1B12 USB1.B1A12 | length 1621.7
  Top Layer w10: FPC2.10 3770.43,4485.05 3808.37,4522.99 R17.2 ; 3776.89,3717.99 3797.84,3717.99 3819.65,3739.79 ; U1.41@3823.59,3587.96 U1.41@3878.71,3643.08 ; U1.41@3823.59,3643.08 U1.41@3878.71,3643.08 ; U1.41@3823.59,3698.2 U1.41@3878.71,3643.08 ; U1.41@3878.71,3587.96 U1.41@3878.71,3643.08 ; U1.41@3878.71,3698.2 U1.41@3878.71,3643.08 ; v1@3896.89,3732.99 3899.03,3732.99 U1.41@3933.83,3698.2 ; U1.41@3933.83,3587.96 U1.41@3878.71,3643.08 ; U1.41@3933.83,3643.08 U1.41@3878.71,3643.08 ; USB1.A1B12@3945.64,5269.55 3967.09,5269.55 USB1.1@3989.73,5292.19 ; 3969.8,3675.02 3946.62,3698.2 U1.41@3933.83,3698.2 ; FPC2.23 4026.34,4485.05 4035.57,4494.27 4061.93,4494.27 4075.65,4507.99 R5.2@4107.23,4507.99 ; U1.41@3878.71,3643.08 U1.41@3933.83,3698.2
  Bottom Layer w10: 3652.22,5137.99 3676.88,5113.33 R14.1 3751.99,5113.33 3776.65,5137.99 3791.89,5137.99 3816.89,5162.99 D4.2@3816.89,5168.52 ; D4.2 D4.2@3816.89,5168.52 ; R13.1 3911.55,5113.33 3881.77,5143.11 3842.3,5143.11 D4.2@3816.89,5168.52 ; D2.1 3947.6,4010.08 CARD1.6 ; 3961.89,5332.99 3989.73,5305.16 USB1.1
  Bottom Layer w23.62: v1(3486.13,5047.99) 3489.47,5044.65 C12.1@3489.47,4967.99 ; C12.1 3492.52,4957.99 3531.89,4918.62 U6.2
  other v1: 3795.63,3363.33 3897.83,3363.33 3661.89,3367.99 3661.89,3427.99 3791.89,3427.99 3896.89,3427.99 3791.89,3507.99 3896.89,3507.99 3556.89,3522.99 3556.89,3582.99 3893.15,3736.73 3711.89,3742.99 3599.64,3769.57 3591.89,3837.99 3948.24,3902.99 4136.89,4027.99 4066.85,4200.19 4102.09,4200.19 4028.9,4277.99 3524.88,4394.93 3626.74,4542.13 3911.89,4558.18 3786.89,4717.99 3816.89,4717.99 3772.45,4742.13 3829.12,4742.13 3801.89,4742.99 3611.74,4750.29 4136.89,4783.31 4081.96,4795.98 4197.44,4801.68 3861.89,4822.99 4191.89,4897.99 3611.74,4912.35 3953.66,4946.97 4186.89,4972.99 3726.42,5025.86 3881.89,5032.99 4011.89,5077.99 3585.47,5097.41 4011.89,5157.99 4171.89,5157.99 3651.89,5177.99 3477.53,5370.43 3781.89,5447.99 3876.75,5447.99
GPIO0: C1.1 H2.14 R1.1 SW1.2 U1.27 | length 1585.4
  Top Layer w10: U1.27 3460.75,3989.14 3416.89,4032.99 3416.89,4597.99 3366.89,4647.99 3541.94,4823.04 v1(3541.94,5082.94) 3541.94,5266.84 SW1.2 3528.31,5284.41 v1(3571.89,5327.99)
  Bottom Layer w10: C1.1 3544.45,5355.43 v1(3571.89,5327.99) ; v1(3541.94,5082.94) 3541.94,5048.28 R1.1
GPIO1: H2.4 U1.39 | length 406.8
  Top Layer w10: U1.39 3545.75,3389.14 v1(3546.89,3387.99)
  Inner2 w10: H2.4@3366.89,3647.99 3471.89,3542.99 3471.89,3462.99 v1(3546.89,3387.99)
GPIO2: H2.5 U1.38 | length 455.1
  Top Layer w10: U1.38 v1(3546.89,3439.14)
  Inner2 w10: H2.5@3366.89,3747.99 3426.89,3687.99 3426.89,3637.99 3491.89,3572.99 3491.89,3494.14 v1(3546.89,3439.14)
GPIO3: H1.13 R5.1 U1.15 | length 617
  Top Layer w10: U1.15 4094.65,4052.67 4181.89,4139.91 4181.89,4507.99 4228.35,4554.45 4255.94,4554.45 4262.4,4547.99 H1.13@4272.4,4547.99
GPIO4: FPC2.22 H1.4 R16.1 U1.4 | length 1473.9
  Top Layer w10: v1(3952.94,3733.86) 4012.87,3673.92 4012.87,3617.01 4140.75,3489.14 U1.4 4184.14,3489.14 4185.43,3490.43 4198.21,3490.43 4221.89,3514.11 4221.89,3567.99 4272.4,3618.5 H1.4@4272.4,3647.99 ; FPC2.22 4006.65,4378.23 v1(4011.89,4372.99)
  Inner2 w10: v1(3952.94,3733.86) 3925.25,3761.55 3925.25,3921.09 3996.89,3992.73 3996.89,4357.99 v1(4011.89,4372.99)
  Bottom Layer w10: v1(4011.89,4372.99) 4011.89,4357.13 4071.03,4297.99 R16.1
GPIO5: FPC2.20 H1.5 R15.1 U1.5 | length 1644.3
  Top Layer w10: v1(3844.6,3765.7) 3953.6,3765.7 4026.89,3692.42 4026.89,3647.99 4135.75,3539.14 U1.5 4181.91,3539.14 4206.89,3564.11 4206.89,3592.99 4221.89,3607.99 4221.89,3667.99 4277.4,3723.5 4277.4,3742.99 H1.5@4272.4,3747.99 ; FPC2.20 3967.28,4377.6 v1(3971.89,4372.99)
  Inner2 w10: v1(3844.6,3765.7) 3844.6,3860.26 3971.89,3987.55 v1(3971.89,4372.99)
  Bottom Layer w10: v1(3971.89,4372.99) 3971.89,4368.33 R15.1
GPIO6: FPC2.18 H1.6 U1.6 | length 1565.8
  Top Layer w10: v1(3794.53,3748.15) 3836.74,3790.36 3948.77,3790.36 4157.06,3582.06 U1.6 4165.28,3587.99 4175.77,3587.99 4206.89,3619.11 4206.89,3782.48 H1.6@4272.4,3847.99 ; FPC2.18 3927.91,4386.97 v1(3941.89,4372.99)
  Inner2 w10: v1(3794.53,3748.15) 3794.53,3836.02 3941.89,3983.38 v1(3941.89,4372.99)
GPIO7: FPC2.16 H1.7 U1.7 | length 1921.6
  Top Layer w10: v1(3771.54,3774.44) 3801.47,3804.37 3954.58,3804.37 4119.81,3639.14 U1.7 ; FPC2.16 3888.54,4432.33 3911.46,4409.41 v1(3911.46,4370.91)
  Inner2 w10: v1(3771.54,3774.44) 3771.54,3832.84 3911.46,3972.77 v1(3911.46,4370.91) 3911.46,4375.08 3949.37,4412.99 4016.89,4412.99 4171.89,4257.99 4171.89,4048.5 4271.89,3948.5 4271.89,3947.99 H1.7@4272.4,3947.99
GPIO8: FPC2.8 H1.12 U1.12 | length 1737.2
  Top Layer w10: v1(3659.54,3927.99) 3686.89,3927.99 3740.43,3874.45 4149.45,3874.45 U1.12 ; FPC2.8 3731.06,4378.12 v1(3734.39,4374.79)
  Inner2 w10: v1(3659.54,3927.99) 3734.39,4002.84 v1(3734.39,4374.79) 3735.45,4375.85 3738.9,4375.85 3737.59,4377.16 3737.59,4423.69 3813.9,4500 4220.39,4500 H1.12@4272.4,4447.99
GPIO9: FPC2.7 H1.15 U1.17 | length 1823.3
  Top Layer w10: FPC2.7 3711.37,4500.67 3895.81,4685.11 3923.47,4685.11 3986.35,4747.99 H1.15@4272.4,4747.99 ; FPC2.7 3711.4,4363.51 3730.92,4343.98 3960.72,4343.98 4000.91,4303.8 4000.91,4236.76 3966.78,4202.64 3747.67,4202.64 3740.35,4195.31 3740.35,4184.25 3745.55,4179.05 3920.65,4179.05 3994.65,4105.06 U1.17
GPIO10: FPC2.6 H1.16 U1.18 | length 1897.6
  Top Layer w10: U1.18 3944.65,4135.24 3914.84,4165.04 3734.84,4165.04 3720.8,4179.08 3720.8,4206.65 3730.8,4216.65 3960.98,4216.65 3986.89,4242.56 3986.89,4297.99 3954.91,4329.97 3705.09,4329.97 3691.69,4343.37 FPC2.6 3691.69,4500.81 3890,4699.12 3917.66,4699.12 4066.53,4847.99 H1.16@4272.4,4847.99
GPIO11: FPC2.5 H1.17 U1.19 | length 1921.7
  Top Layer w10: U1.19 3893.96,4040.21 3893.96,4132.89 3875.83,4151.02 3725.72,4151.02 3706.79,4169.96 3706.79,4217.71 3719.74,4230.67 3944.43,4230.67 3971.89,4258.12 3971.89,4287.99 3943.93,4315.95 3699.29,4315.95 3672,4343.24 FPC2.5 3672,4500.94 3884.19,4713.14 3911.86,4713.14 4146.71,4947.99 H1.17@4272.4,4947.99
GPIO12: FPC2.4 H1.18 U1.20 | length 1944.8
  Top Layer w10: U1.20 3844.65,4120.24 3827.87,4137.01 3719.92,4137.01 3692.77,4164.16 3692.77,4223.52 3713.94,4244.68 3938.58,4244.68 3956.89,4262.99 3956.89,4283.17 3938.12,4301.94 3693.48,4301.94 3652.32,4343.1 FPC2.4 3652.32,4501.09 3878.39,4727.15 3906.05,4727.15 4226.89,5047.99 H1.18@4272.4,5047.99
GPIO13: FPC2.3 H1.19 U1.21 | length 2018.4
  Top Layer w10: U1.21 3794.65,4052.01 3813.86,4071.22 3813.86,4112.99 3803.86,4122.99 3714.11,4122.99 3678.76,4158.35 3678.76,4229.32 3708.13,4258.7 3932.31,4258.7 3942.56,4268.95 3942.56,4277.68 3932.32,4287.92 3687.68,4287.92 3632.63,4342.97 FPC2.3 3632.63,4501.22 3872.58,4741.17 3900.25,4741.17 4272.4,5113.33 H1.19@4272.4,5147.99
GPIO14: H1.20 U1.22 | length 1747
  Top Layer w10: v1(3655.76,4198.41) 3655.76,4141.19 3744.65,4052.3 U1.22
  Inner2 w10: v1(3655.76,4198.41) 3655.76,5051.87 3791.89,5187.99 4212.4,5187.99 H1.20@4272.4,5247.99
GPIO15: FPC2.13 H1.8 U1.8 | length 1979.2
  Top Layer w10: v1(3693.05,3809.41) 3702.03,3818.39 4022.11,3818.39 4151.36,3689.14 U1.8 ; FPC2.13 3829.48,4402.89 3852.37,4380 3852.37,4369.75 v1(3853.26,4368.86)
  Inner2 w10: v1(3693.05,3809.41) 3693.05,3841.82 3853.26,4002.02 v1(3853.26,4368.86) 3853.26,4382.77 3842.56,4393.47 3842.56,4418.66 3856.89,4432.99 4016.89,4432.99 4186.89,4262.99 4186.89,4133.5 H1.8@4272.4,4047.99
GPIO16: FPC2.12 H1.9 U1.9 | length 1920.1
  Top Layer w10: v1(3663.77,3837.5) 3668.87,3832.4 4056.73,3832.4 4149.99,3739.14 U1.9 ; FPC2.12 3809.8,4383.94 v1(3823.26,4370.48)
  Inner2 w10: v1(3663.77,3837.5) 3668.91,3837.5 3823.26,3991.85 v1(3823.26,4370.48) 3823.26,4429.54 3851.67,4457.95 4021.93,4457.95 4201.89,4277.99 4201.89,4218.5 H1.9@4272.4,4147.99
GPIO17: FPC2.11 H1.10 U1.10 | length 1827.1
  Top Layer w10: v1(3661.89,3867.99) 3676.03,3867.99 3697.6,3846.42 4092.71,3846.42 4149.99,3789.14 U1.10 ; FPC2.11 3790.11,4371.11 v1(3792.58,4368.64)
  Inner2 w10: v1(3661.89,3867.99) 3664.64,3867.99 3792.58,3995.93 v1(3792.58,4368.64) 3792.58,4418.69 3845.87,4471.97 4048.42,4471.97 H1.10@4272.4,4247.99
GPIO18: FPC2.9 H1.11 U1.11 | length 1770.6
  Top Layer w10: v1(3662.13,3897.99) 3686.89,3897.99 3724.45,3860.43 4124.45,3860.43 4145.75,3839.14 U1.11 ; FPC2.9 3750.74,4396.52 v1(3764.39,4382.87)
  Inner2 w10: v1(3662.13,3897.99) 3666.71,3897.99 3764.39,3995.67 v1(3764.39,4382.87) 3764.39,4425.49 3824.88,4485.98 4134.41,4485.98 H1.11@4272.4,4347.99
GPIO19: H2.20 R3.2 U1.13 | length 2095.9
  Top Layer w11.92: v1(4049.49,3901.79) 4088.1,3940.39 4162.88,3940.39 U1.13
  Inner2 w10: v1(4023.9,4243.33) 4043.86,4223.37 4043.86,3907.42 v1(4049.49,3901.79)
  Bottom Layer w10: H2.20@3366.89,5247.99 3368.15,5249.25 3465.97,5249.25 R3.2
  Bottom Layer w11.92: R3.2 3496.89,5218.33 3496.89,5127.99 3495.05,5126.15 3495.05,5126.04 3488.05,5119.04 3487.94,5119.04 3451.89,5082.99 3451.89,4407.99 3591.89,4267.99 3999.24,4267.99 v1(4023.9,4243.33)
GPIO20: H2.19 R4.2 U1.14 | length 2087.1
  Top Layer w11.92: v1(4017.63,3902.44) 4017.63,3907.44 4100.58,3990.39 4157.88,3990.39 4159.14,3989.14 U1.14
  Inner2 w10: v1(4017.63,3902.44) 4017.63,4205.74 v1(4019.88,4207.99)
  Bottom Layer w10: H2.19@3366.89,5147.99 3368.15,5149.25 3465.97,5149.25 R4.2
  Bottom Layer w11.92: R4.2 3431.89,5112.65 3431.89,4292.99 3476.89,4247.99 3979.88,4247.99 v1(4019.88,4207.99)
GPIO21: H2.18 U1.23 | length 1144.2
  Top Layer w10: v1(3611.89,4183.26) 3611.89,4137.99 3694.65,4055.24 U1.23
  Inner2 w10: H2.18@3366.89,5047.99 3576.89,4837.99 3576.89,4554.46 3611.89,4519.46 ; v1@3611.89,4188.26 3611.89,4519.46 ; 3611.89,4524.46 3611.89,4519.46
GPIO38: H2.10 U1.31 U2.2 | length 914.4
  Top Layer w10: U1.31 3481.3,3782.99 3491.3,3792.99 3491.79,3792.99 3531.89,3833.09 v1(3531.89,3842.99)
  Inner2 w10: H2.10@3366.89,4247.99 3531.89,4082.99 ; v1(3531.89,3842.99) 3531.89,4082.99 ; v1(3586.89,4367.99) 3588.9,4365.98 3588.9,4125 3546.89,4082.99 3531.89,4082.99
  Bottom Layer w10: U2.2 3586.89,4393.78 v1(3586.89,4367.99)
GPIO39: CARD1.3 D3.2 H2.9 R12.2 U1.32 | length 1236.9
  Top Layer w10: U1.32 3485.16,3749.14 3497.93,3749.14 3516.79,3767.99 v1(3536.89,3767.99)
  Inner2 w10: H2.9@3366.89,4147.99 3421.89,4147.99 3501.89,4067.99 3501.89,3802.99 v1(3536.89,3767.99)
  Bottom Layer w10: v1(3536.89,3767.99) 3596.89,3707.99 3786.89,3707.99 3818.69,3739.79 3818.69,3956.03 CARD1.3 3819.68,3959.05 D3.2 3819.68,4096.13 R12.2@3821.89,4098.33
GPIO40: CARD1.5 D2.2 H2.8 R11.2 U1.33 | length 1222.2
  Top Layer w10: U1.33 3476.3,3687.99 v1(3536.89,3687.99)
  Inner2 w10: H2.8@3366.89,4047.99 3366.89,4037.99 3456.89,3947.99 3456.89,3767.99 v1(3536.89,3687.99)
  Bottom Layer w10: v1(3536.89,3687.99) 3811.89,3687.99 3906.89,3782.99 3906.89,3954.44 CARD1.5 3909.09,3961.85 D2.2 3909.09,4096.22 R11.2@3911.89,4099.01
GPIO41: CARD1.7 D1.2 H2.7 R10.2 U1.34 | length 1323.4
  Top Layer w10: H2.7@3366.89,3947.99 3412.13,3902.76 3412.13,3862.83 3434.64,3840.31 3434.64,3816.87 3436.89,3814.62 3436.89,3813.65 3434.64,3811.4 3434.64,3766.87 3436.89,3764.62 3436.89,3763.65 3434.64,3761.4 3434.64,3666.87 3462.38,3639.14 U1.34 3485.16,3629.14 v1(3536.89,3629.14)
  Bottom Layer w10: v1(3536.89,3629.14) 3933.03,3629.14 3991.89,3687.99 3991.89,3956.06 CARD1.7 3994.09,3960.23 D1.2 3994.09,4095.54 R10.2@3996.89,4098.33
GPIO42: H2.6 U1.35 | length 311.2
  Top Layer w10: H2.6@3366.89,3847.99 3416.89,3797.99 3416.89,3634.62 3462.38,3589.14 U1.35
GPIO45: H2.15 R7.2 U1.26 | length 797.8
  Top Layer w10: v1(3469.37,4314.3) 3451.89,4296.82 3451.89,4143.33 R7.2 3544.65,4050.58 U1.26
  Inner2 w10: H2.15@3366.89,4747.99 3469.37,4645.51 v1(3469.37,4314.3)
GPIO46: H1.14 R6.1 U1.16 | length 753.8
  Top Layer w10: U1.16 4044.65,4055.75 4096.89,4107.99 R6.1 4161.89,4168.33 4161.89,4302.51 4162.91,4303.54 4162.91,4441.97 4141.89,4462.99 4141.89,4562.99 4231.89,4652.99 4267.4,4652.99 H1.14@4272.4,4647.99
GPIO47: H2.17 U1.24 | length 1038.2
  Top Layer w10: v1(3556.89,4197.99) 3556.89,4152.99 3644.65,4065.24 U1.24
  Inner2 w10: H2.17@3366.89,4947.99 3391.89,4947.99 3547.87,4792.01 3547.87,4207.01 v1(3556.89,4197.99)
GPIO48: H2.16 U1.25 | length 902.8
  Top Layer w10: v1(3544.88,4122.99) 3594.65,4073.23 U1.25
  Inner2 w10: H2.16@3366.89,4847.99 3501.89,4712.99 3501.89,4175.48 3544.88,4132.48 v1(3544.88,4122.99)
LED_RGB: R9.2 U2.4 | length 115.2
  Top Layer w10: v1(3524.88,4462.99) 3543.93,4482.04 R9.2
  Bottom Layer w10: v1(3524.88,4462.99) 3544.49,4482.6 U2.4
RST: C2.1 C3.2 H1.3 R2.1 SW2.2 U1.3 | length 2150.7
  Top Layer w10: v1(4082.36,4997.99) 4082.36,5243.46 4114.92,5276.02 SW2.2 4114.92,5346.02 v1(4116.89,5347.99) ; U1.3 4176.91,3439.14 4272.4,3534.62 H1.3@4272.4,3547.99
  Bottom Layer w10: C2.1 4155.08,5350.43 C3.2 ; v1(4082.36,4997.99) 4082.36,4966.76 4089.37,4959.75 4089.37,4959.43 4095.8,4952.99 4096.12,4952.99 4174.45,4874.67 4174.45,4430.21 R2.1 4167.23,4417.65 4199.45,4385.43 4199.45,3620.94 H1.3@4272.4,3547.99
RX: H2.3 U1.36 | length 111.9
  Top Layer w10: H2.3@3366.89,3547.99 3375.75,3539.14 U1.36
TX: H2.2 U1.37 | length 125.3
  Top Layer w10: H2.2@3366.89,3447.99 3408.01,3489.14 U1.37
pads on no net: CARD1.1 CARD1.2 CARD1.8 CARD1.CD FPC2.1 FPC2.2 FPC2.24 H2.11 H2.12 H2.13 LED2.2 U1.28 U1.29 U1.30 U5.4 U6.4 USB1.A8 USB1.B8

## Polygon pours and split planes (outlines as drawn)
GND on Top Layer (solid, remove dead copper, pour order 2): 3307.99,5513.17 3307.99,3293.27 4331.61,3293.27 4331.61,5513.17
+VUSB on Inner2 (solid, remove dead copper): 3526.55,5513.17 3526.55,5196.11 4106.44,5196.11 4106.44,5513.17
+VIN on Inner2 (solid, remove dead copper): 4316.89,5497.99 4321.89,5497.99 4321.89,5213.67 4111.6,5213.67 4111.6,5497.99
GND on Top Layer (solid, remove dead copper, pour order 0): 3297.99,5513.17 3297.99,3293.27 4321.61,3293.27 4321.61,5513.17
GND on Bottom Layer (solid, remove dead copper, pour order 6): 3292.99,5532.99 3292.99,3310.81 4351.89,3310.81 4351.89,5532.99
+3.3V on Bottom Layer (solid, remove dead copper, pour order 4): 3993.49,4436.69 4013.29,4436.69 3908.47,4632.48 4164.91,4632.48 4164.91,4456.01 4161.89,4452.99 4161.89,4234.02 4171.89,4224.02 4126.18,4224.02 4112.2,4237.99 4112.2,4317.68 4001.55,4428.33 4001.55,4433.33 3996.86,4433.33
GND on Inner2 (solid, remove dead copper): 4049.39,4150.49 4161.89,4150.49 4161.89,4247.8 4041.89,4367.8 4041.89,4367.99 4026.46,4367.99 4026.46,4367.56 4011.89,4352.99 4011.89,4267.99 4026.89,4252.99 4036.89,4252.99 4049.39,4240.49
+3.3V on Inner2 (solid, remove dead copper): 3644.65,4927.62 3644.65,4010.24 4338.42,4010.24 4338.42,4927.62
GND on Inner2 (solid, remove dead copper): 3302.99,5513.17 3302.99,3293.27 4339.81,3293.27 4339.81,5513.17
+VSYS on Inner2 (solid, remove dead copper): 3639.78,5188.76 3639.78,4937.99 4332.14,4937.99 4332.14,5188.76
+3.3V on Inner2 (solid, remove dead copper): 3590.55,4072.68 3590.55,3292.99 4338.42,3292.99 4338.42,4072.68
GND on Inner3 (solid, remove dead copper): 3302.99,5513.17 3302.99,3293.27 4338.42,3293.27 4338.42,5513.17

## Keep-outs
Top Layer:
  region: 3311.89,3290.82 3311.89,3031.02 4326.89,3031.02 4326.89,3290.82
  region: 3386.89,4007.99 3386.89,3987.99 3406.89,3987.99 3406.89,4007.99
  region: 3391.89,3607.99 3391.89,3587.99 3411.89,3587.99 3411.89,3607.99
  region: 3391.89,3514.45 3391.89,3494.45 3411.89,3494.45 3411.89,3514.45
  region: 4218.35,4624.11 4218.35,4574.11 4238.35,4574.11 4238.35,4624.11
  region: 3761.89,5357.99 3761.89,5337.99 3881.89,5337.99 3881.89,5357.99
Inner2:
  region: 3811.89,3757.99 3811.89,3742.99 3886.89,3742.99 3886.89,3757.99
  region: 3944.39,3900.49 3944.39,3885.49 4019.39,3885.49 4019.39,3900.49
  region: 4054.39,3975.49 4054.39,3960.49 4234.39,3960.49 4234.39,3975.49
  region: 4219.39,4035.49 4219.39,4020.49 4249.39,4020.49 4249.39,4035.49
  region: 4221.89,4120.49 4221.89,4105.49 4251.89,4105.49 4251.89,4120.49
  region: 4231.89,4215.49 4231.89,4200.49 4261.89,4200.49 4261.89,4215.49
  region: 4221.89,4425.49 4221.89,4410.49 4251.89,4410.49 4251.89,4425.49
  region: 3354.65,4905.91 3354.65,4890.91 3384.65,4890.91 3384.65,4905.91
  region: 3354.64,4805.35 3354.64,4790.35 3384.64,4790.35 3384.64,4805.35
Bottom Layer:
  region: 4056.89,5147.99 4056.89,5127.99 4101.89,5127.99 4101.89,5147.99
  region: 3486.89,4447.99 3486.89,4392.99 3506.89,4392.99 3506.89,4447.99
Board Outline Layer:
  the board outline again, w10

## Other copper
Bottom Layer:
  region net +3.3V: 3977.83,4767.92 3983.03,4791.54 4002.73,4791.92 4022.4,4793.06 4017.2,4765.95 4004.11,4767.04 3990.98,4767.7 3977.83,4767.92

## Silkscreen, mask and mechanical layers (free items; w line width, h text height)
Top Silkscreen Layer:
  drawing of 22 lines, arcs and shapes, not listed
  text "GND" at 3399.65,5492.29 h47.24 r270
  text "GND" at 4191.89,5487.99 h47.24 r270
  text "GND" at 3399.65,5387.29 h47.24 r270
  text "VIN" at 4191.89,5382.99 h47.24 r270
  text "19" at 3399.65,5269.29 h47.24 r270
  text "14" at 4191.89,5267.99 h47.24 r270
  text "BOOT" at 3461.89,5197.99 h51.18
  text "RST" at 4072.62,5197.73 h51.18
  text "*13" at 4191.89,5182.99 h47.24 r270
  text "20" at 3399.65,5181.69 h47.24 r270
  text "*12" at 4191.89,5087.99 h47.24 r270
  text "21" at 3399.65,5068.19 h47.24 r270
  text "*11" at 4191.89,4977.99 h47.24 r270
  text "47" at 3399.65,4976.74 h47.24 r270
  text "*10" at 4191.89,4882.99 h47.24 r270
  text "48" at 3399.65,4876.74 h47.24 r270
  text "45" at 3399.65,4775.49 h47.24 r270
  text "*9" at 4191.89,4772.99 h47.24 r270
  text "NeuroBoard S3" at 3526.89,4742.99 h86.61
  text "*CAM / ^RGB / ~SD" at 3846.89,4697.99 h51.18 r270
  text "46" at 4191.89,4672.99 h47.24 r270
  text "0" at 3399.65,4663.19 h47.24 r270
  text "NC" at 3399.65,4580.49 h47.24 r270
  text "3" at 4191.89,4557.99 h47.24 r270
  text "NC" at 3399.65,4475.49 h47.24 r270
  text "*8" at 4191.89,4472.99 h47.24 r270
  text "*18" at 4191.89,4382.99 h47.24 r270
  text "NC" at 3399.65,4380.49 h47.24 r270
  text "^38" at 3396.89,4297.99 h47.24 r270
  text "*17" at 4191.89,4282.99 h47.24 r270
  text "~39" at 3399.65,4193.99 h47.24 r270
  text "*16" at 4191.89,4182.99 h47.24 r270
  text "~40" at 3399.65,4096.49 h47.24 r270
  text "*15" at 4191.89,4082.99 h47.24 r270
  text "~41" at 3399.65,3990.39 h47.24 r270
  text "*7" at 4191.89,3972.99 h47.24 r270
  text "42" at 3399.65,3872.99 h47.24 r270
  text "*6" at 4191.89,3872.99 h47.24 r270
  text "*5" at 4191.89,3772.99 h47.24 r270
  text "2" at 3399.65,3757.99 h47.24 r270
  text "*4" at 4191.89,3672.99 h47.24 r270
  text "1" at 3399.65,3654.29 h47.24 r270
  text "RST" at 4191.89,3587.99 h47.24 r270
  text "RX" at 3399.65,3573.19 h47.24 r270
  text "3V3" at 4191.89,3492.99 h47.24 r270
  text "TX" at 3396.89,3477.99 h47.24 r270
  text "3V3" at 4191.89,3392.99 h47.24 r270
  text "GND" at 3399.65,3392.29 h47.24 r270
  text "magasin@ece.fr" at 3586.89,3292.99 h62.99
Bottom Silkscreen Layer:
  region: 4133.74,3137.4 4133.74,3216.14 3936.89,3216.14 3936.89,3137.4
  text "V3" at 3866.89,5427.99 h62.99
  text "Designed by  / Virgile BEAUFILS / For education use only" at 3421.89,3967.99 h55.12 r270
  text "Oups !" at 3996.89,3577.99 h120
  text "AI,  / From Silicon  / To Cloud" at 3881.89,3062.99 h62.99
